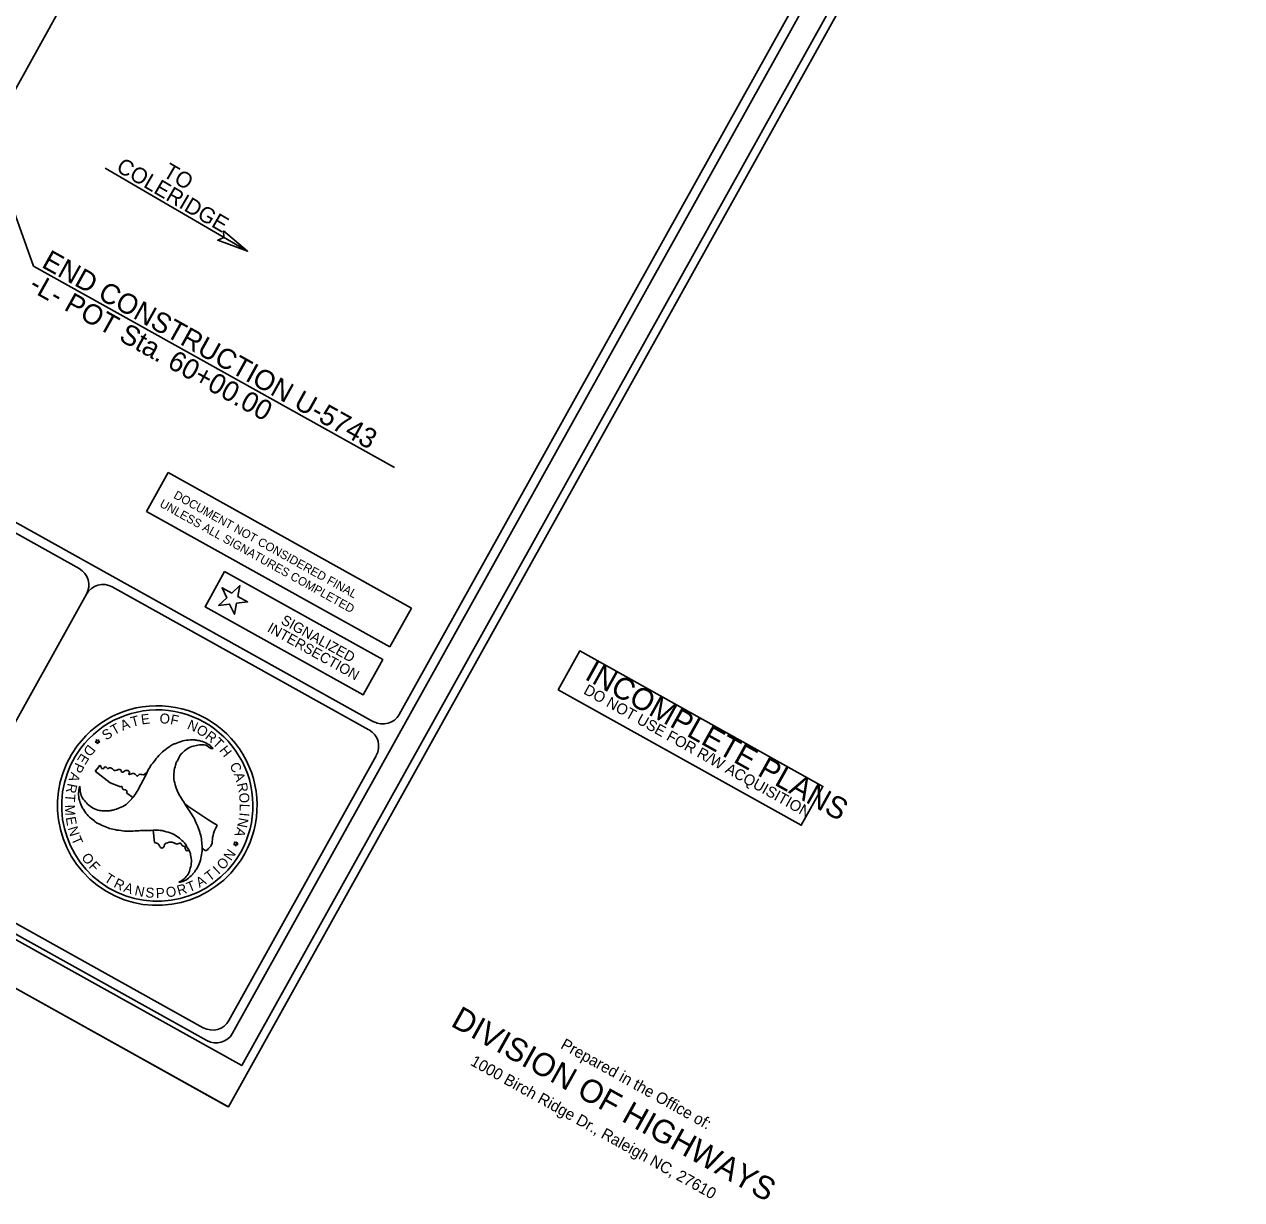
# Model space of a CAD drawing. Extents: x 1754939 to 1770240, y 706534 to 717510.
# Drawn here: x 1766382 to 1770240, y 706534 to 710258 of the extents above; entities that cross this region are included whole.
import ezdxf

# ---------------------------------------------------------------- set-up
doc = ezdxf.new("R2010")
doc.units = 0
for name, color, linetype in [('Culvert Barrel', 7, 'Continuous'), ('Culvert Wing', 7, 'Continuous'), ('ENG SEALS CELL', 7, 'Continuous'), ('Prop Conc 4in Sidewalk', 7, 'Continuous'), ('Prop Conc Drive Radius Type', 7, 'Continuous'), ('Prop EOT Dash', 7, 'Continuous'), ('Prop Guardrail Anchor Unit CELL', 7, 'Continuous'), ('Prop Lane Arrow CELL', 7, 'Continuous'), ('Prop SS Cut Line', 7, 'Continuous'), ('Prop Structure Anchor Unit CELL', 7, 'Continuous'), ('Prop Terminator CELL', 7, 'Continuous'), ('Sheet PE Seal Cell', 7, 'Continuous')]:
    doc.layers.add(name, color=color, linetype=linetype)

msp = doc.modelspace()

# ---------------------------------------------------------------- linework, layer by layer
at = {"layer": 'Culvert Barrel'}
for p, q in [((1758201.2, 711744), (1767028.7, 706828.1)), ((1767026.1, 706829.6), (1758201.2, 711744))]:
    msp.add_line(p, q, dxfattribs=at)
at = {"layer": 'Culvert Wing'}
msp.add_lwpolyline([(1770239.7, 712594.3), (1761412.2, 717510.1), (1758201.2, 711744), (1767028.7, 706828.1)], close=True, dxfattribs=at)
at = {"layer": 'ENG SEALS CELL'}
msp.add_lwpolyline([(1764850.1, 710295.2), (1764850.1, 710295.2), (1765360.9, 711212.6), (1765360.9, 711212.6), (1766611.7, 710516), (1766483.1, 710285.1), (1766100.9, 709598.7)], close=True, dxfattribs=at)
at = {"layer": 'Prop Conc 4in Sidewalk'}
for p, q in [((1766769.2, 708714.5), (1766837.8, 708837.7)), ((1766837.8, 708837.7), (1767608.4, 708408.6)), ((1767539.8, 708285.4), (1766769.2, 708714.5)), ((1767608.3, 708408.5), (1767539.7, 708285.3))]:
    msp.add_line(p, q, dxfattribs=at)
at = {"layer": 'Prop Conc Drive Radius Type'}
for p, q in [((1760044.9, 712193.8), (1767488.6, 708048.6)), ((1765508.2, 709117), (1766555.4, 708533.9)), ((1766660.3, 708475.5), (1767474, 708022.3)), ((1766111.6, 707613.5), (1766578.6, 708452.3)), ((1766606.6, 707983.2), (1766611, 707986.5)), ((1766611.9, 707983.3), (1766606.6, 707983.2)), ((1766611, 707986.5), (1766609.4, 707991.7)), ((1766609.4, 707991.7), (1766613.9, 707988.4)), ((1766613.6, 707978), (1766611.9, 707983.3)), ((1766615.4, 707983.2), (1766613.6, 707978)), ((1766613.9, 707988.4), (1766618.1, 707991.6)), ((1766620.9, 707983.2), (1766615.4, 707983.2)), ((1766618.1, 707991.6), (1766616.6, 707986.4)), ((1766616.6, 707986.4), (1766620.9, 707983.2)), ((1766979.7, 707963.8), (1766978.9, 707963.6)), ((1766979.7, 707963.8), (1766978.9, 707963.6)), ((1766606.6, 707892.2), (1766618.5, 707907.1)), ((1766653.4, 707854.6), (1766606.6, 707892.2)), ((1766687, 707842.1), (1766653.4, 707854.6)), ((1766725.8, 707808), (1766705.9, 707823.2)), ((1766890.8, 707787.8), (1766890.8, 707787.8)), ((1766794.1, 707665.6), (1766790, 707704.5)), ((1766790, 707704.5), (1766790, 707704.5)), ((1767049.2, 707662.3), (1767044.8, 707659)), ((1767051.8, 707664.3), (1767047.5, 707667.5)), ((1767047.5, 707667.5), (1767049.2, 707662.3)), ((1767056.2, 707667.3), (1767051.8, 707664.3)), ((1767054.7, 707662.2), (1767056.2, 707667.3)), ((1767059.1, 707659.1), (1767054.7, 707662.2)), ((1767044.8, 707659), (1767050.1, 707659.1)), ((1767050.1, 707659.1), (1767051.7, 707653.9)), ((1767051.7, 707653.9), (1767053.5, 707659)), ((1767053.5, 707659), (1767059.1, 707659.1)), ((1767056.7, 707594), (1767056.7, 707594))]:
    msp.add_line(p, q, dxfattribs=at)
for points in [[(1767041.7, 707061.2), (1770048.4, 712460.4)], [(1767570.1, 708071.7), (1770007.7, 712448.9)], [(1759201.9, 711358.3), (1766960.1, 707037.9)], [(1767030.1, 707102), (1767497.2, 707940.7)], [(1766134.8, 707531.9), (1766948.5, 707078.8)]]:
    msp.add_lwpolyline(points, dxfattribs=at)
for centre, radius, start, end in [((1766526.2, 708481.5), 60, 330.8875, 60.8875), ((1766631.1, 708423.1), 60, 60.8875, 150.8875), ((1766803.1, 707782.9), 316.3, 323.3087, 143.3087), ((1766803.1, 707782.9), 303.1, 323.3087, 143.3087), ((1767517.9, 708101.2), 60, 240.8875, 330.8875), ((1767444.9, 707970.2), 60, 330.8875, 60.8875), ((1766803.1, 707782.9), 316.3, 143.3087, 323.3087), ((1766803.1, 707782.9), 303.1, 143.3087, 323.3087), ((1767860.9, 709144.3), 1667.7, 228.9872, 229.0868), ((1767860.9, 709144.3), 1667.7, 234.4262, 238.6322), ((1766977.9, 707131.4), 60, 240.8875, 330.8875), ((1766989.5, 707090.6), 60, 240.8875, 330.8875)]:
    msp.add_arc(centre, radius, start, end, dxfattribs=at)
for points in [[(1766978.9, 707963.6), (1766974.3, 707969.4), (1766956.9, 707981.2), (1766935.7, 707988.5), (1766933.6, 707988.8), (1766921.6, 707990.7), (1766907.5, 707990.7), (1766884.1, 707988), (1766861.6, 707979.8), (1766852.3, 707976.1), (1766842.9, 707970), (1766824, 707956.3), (1766808.1, 707941.2), (1766792, 707921.8), (1766779, 707903.8), (1766768.5, 707883.5), (1766758, 707862.9), (1766747.4, 707843.2), (1766736.3, 707823.1), (1766722.9, 707804.9), (1766721.6, 707803.4), (1766704, 707786.5), (1766683.6, 707775.4), (1766662.9, 707768.7), (1766652.1, 707766.6), (1766638.7, 707766.3), (1766631, 707766), (1766615.1, 707768.7), (1766594.7, 707777.6), (1766578.5, 707791.2), (1766566.3, 707806.3), (1766559.4, 707824.6), (1766558, 707844.6)], [(1766871.7, 707539.6), (1766878.7, 707540.8), (1766897.8, 707549.8), (1766914.7, 707564.5), (1766916.2, 707566.1), (1766923.6, 707575.7), (1766930.8, 707588), (1766940.3, 707609.5), (1766944.2, 707633.1), (1766945.8, 707643), (1766945.2, 707654.3), (1766942.8, 707677.5), (1766937.7, 707698.7), (1766928.9, 707722.4), (1766919.6, 707742.5), (1766907.5, 707762), (1766894.9, 707781.2), (1766883.2, 707800.1), (1766871.1, 707820.1), (1766862.2, 707840.7), (1766861.7, 707842.6), (1766855.6, 707866.5), (1766856.3, 707889.7), (1766860.7, 707910.9), (1766864.5, 707921), (1766871, 707932.9), (1766874.5, 707939.9), (1766884.9, 707952), (1766902.8, 707965.4), (1766922.5, 707972.6), (1766941.7, 707975.5), (1766961.1, 707972.3), (1766978.9, 707963.6), (1766979.7, 707963.8)], [(1766618.5, 707907.1), (1766619, 707908.9), (1766622.8, 707908.7), (1766627.8, 707900.4), (1766633.7, 707900.8), (1766635.8, 707904), (1766641, 707905), (1766645.1, 707900.3), (1766653.8, 707902.7), (1766658.6, 707900.6), (1766667.1, 707894.2), (1766684.9, 707896.9), (1766689.6, 707894.3), (1766688.7, 707890.8), (1766690.9, 707888.3), (1766701.6, 707893.5), (1766703.6, 707893.9), (1766713.9, 707891.1), (1766714.9, 707888), (1766712.7, 707883.8), (1766713.2, 707882.2), (1766717.3, 707882.1), (1766724.2, 707884), (1766733.2, 707882.5), (1766740, 707876.1), (1766745.8, 707881.2), (1766758.9, 707880.6), (1766763.3, 707882.8), (1766766.5, 707886)], [(1766768.7, 707884), (1766768.5, 707883.5), (1766758, 707862.9), (1766747.4, 707843.2), (1766736.3, 707823.1), (1766725.7, 707808.1)], [(1766558, 707844.6), (1766555.6, 707837.5), (1766553.9, 707816.6), (1766558, 707794.6), (1766558.9, 707792.7), (1766563.3, 707781.2), (1766570.4, 707769.1), (1766584.4, 707750), (1766602.7, 707735), (1766610.5, 707728.6), (1766620.9, 707723.4), (1766641.9, 707714.1), (1766662.7, 707707.8), (1766687.8, 707703.5), (1766709.6, 707701.4), (1766732.7, 707702.3), (1766755.7, 707703.7), (1766778.1, 707704.2), (1766801.1, 707704.5), (1766823.6, 707702.2), (1766825.8, 707701.5), (1766849.3, 707694.8), (1766868.9, 707682.8), (1766884.9, 707668.5), (1766892.4, 707660), (1766898.9, 707648.5), (1766903.5, 707641.9), (1766908.8, 707626.8), (1766911.2, 707604.8), (1766907.7, 707584.1), (1766900.6, 707565.8), (1766888.2, 707550.7), (1766871.7, 707539.6)], [(1766705.9, 707823.2), (1766706.6, 707828.3), (1766703.6, 707832.4), (1766696.2, 707833.5), (1766692.4, 707836.7), (1766690.4, 707843.1), (1766687, 707842.1)], [(1766946, 707647.1), (1766945.2, 707654.3), (1766942.8, 707677.5), (1766937.7, 707698.7), (1766928.9, 707722.4), (1766919.6, 707742.5), (1766907.5, 707762), (1766894.9, 707781.2), (1766890.8, 707787.8)], [(1766790, 707704.5), (1766801.1, 707704.5), (1766823.6, 707702.2), (1766825.8, 707701.5), (1766849.3, 707694.8), (1766868.9, 707682.8), (1766884.9, 707668.5), (1766892.4, 707660), (1766898.9, 707648.5), (1766903.1, 707642.3)], [(1766992.8, 707720.3), (1766983.8, 707700.7), (1766977.8, 707674.2), (1766975.4, 707659), (1766968.3, 707649.7), (1766957.8, 707640.2), (1766946.1, 707647.1)], [(1766903, 707642.3), (1766897.3, 707639.6), (1766893.3, 707642.1), (1766890.6, 707652.5), (1766881.1, 707656.9), (1766879, 707661.9), (1766876.6, 707663.8), (1766865.1, 707660.8), (1766855.6, 707665), (1766835.3, 707665.1), (1766828.3, 707661.5), (1766820.3, 707648.6), (1766815.2, 707648.6), (1766811.8, 707652.1), (1766806, 707661.3), (1766794.1, 707665.6)]]:
    msp.add_spline(points, degree=3, dxfattribs=at)
at = {"layer": 'Prop EOT Dash'}
msp.add_lwpolyline([(1767016.6, 708524.5), (1767517.9, 708245.4), (1767455.7, 708133.7), (1766954.4, 708412.8)], close=True, dxfattribs=at)
at = {"layer": 'Prop Guardrail Anchor Unit CELL'}
msp.add_lwpolyline([(1767012.5, 709603.5), (1767089.2, 709539.1), (1766994.7, 709573.9), (1767014.4, 709582.7)], close=True, dxfattribs=at)
at = {"layer": 'Prop Lane Arrow CELL'}
msp.add_lwpolyline([(1758334.8, 711823.6), (1767070.6, 706958.9), (1770150.6, 712489.7), (1761414.8, 717354.5), (1758334.8, 711823.6)], dxfattribs=at)
at = {"layer": 'Prop SS Cut Line'}
for p, q in [((1766208.9, 710057.9), (1766410.5, 709491.6)), ((1766410.5, 709491.6), (1767554.9, 708854.4))]:
    msp.add_line(p, q, dxfattribs=at)
at = {"layer": 'Prop Structure Anchor Unit CELL'}
msp.add_lwpolyline([(1767039.3, 708456), (1767008.4, 708473.2), (1767023.2, 708441.1), (1766997.3, 708417), (1767032.5, 708421.2), (1767047.4, 708389.1), (1767054.2, 708423.9), (1767089.3, 708428.1), (1767058.4, 708445.3), (1767065.2, 708480.1), (1767039.3, 708456)], dxfattribs=at)
at = {"layer": 'Prop Terminator CELL'}
msp.add_lwpolyline([(1768073.5, 708149.6), (1768142.1, 708272.8), (1768912.6, 707843.6), (1768844, 707720.5)], close=True, dxfattribs=at)
at = {"layer": 'Sheet PE Seal Cell'}
msp.add_line((1766637.9, 709802.4), (1767089.2, 709539.1), dxfattribs=at)

# ---------------------------------------------------------------- texts
at = {"layer": 'Prop Conc 4in Sidewalk'}
for s, p in [('DOCUMENT NOT CONSIDERED FINAL', (1766852.4, 708758.5)), ('UNLESS ALL SIGNATURES COMPLETED', (1766808.3, 708731.3))]:
    msp.add_text(s, height=27, rotation=330.8875, dxfattribs=at).set_placement(p)
at = {"layer": 'Prop Conc Drive Radius Type'}
for s, height, rotation, p in [('T', 31.6, 28.6888, (1766666, 708005.4)), ('A', 31.6, 21.6365, (1766693.3, 708019.9)), ('T', 31.5, 14.5812, (1766723.6, 708031.9)), ('E', 31.4, 7.4656, (1766753.5, 708039.5)), ('O', 31.6, 355.5262, (1766809.3, 708044)), ('F', 31.6, 348.3794, (1766842.5, 708041.2)), ('N', 31.5, 336.2925, (1766895.6, 708027.3)), ('S', 31.5, 35.0649, (1766641.4, 707988.2)), ('O', 31.6, 328.7943, (1766923.8, 708014.7)), ('R', 31.5, 322.1844, (1766952.3, 707997.4)), ('D', 31.5, 231.1617, (1766585.2, 707978.7)), ('T', 31.6, 315.5348, (1766976.1, 707979)), ('H', 31.5, 308.4501, (1766998, 707957.2)), ('E', 31.4, 237.4496, (1766562.8, 707950.3)), ('P', 31.5, 244.982, (1766544.8, 707921.1)), ('C', 31.4, 296.1077, (1767031.2, 707910.7)), ('A', 31.5, 251.5745, (1766530.6, 707890.5)), ('A', 31.5, 288.6107, (1767044.9, 707882.3)), ('R', 31.5, 282.2467, (1767055.3, 707851.7)), ('T', 31.5, 265.2937, (1766512.7, 707820.8)), ('R', 31.5, 258.6432, (1766519.2, 707854.9)), ('O', 31.6, 275.1271, (1767061.6, 707822.2)), ('M', 31.5, 272.5287, (1766510.2, 707785)), ('L', 31.5, 268.8935, (1767064.6, 707788.8)), ('E', 31.5, 279.9955, (1766512.7, 707745)), ('N', 31.5, 259.204, (1767061.9, 707746.2)), ('I', 31.6, 264.9041, (1767063.5, 707761.5)), ('N', 31.6, 286.9671, (1766519, 707711.5)), ('A', 31.5, 251.772, (1767055.9, 707715.9)), ('T', 31.5, 293.8091, (1766529.7, 707677.6)), ('O', 31.5, 307.1127, (1766560.9, 707618)), ('N', 31.5, 55.5168, (1767036.8, 707605.6)), ('F', 31.5, 314.278, (1766584.3, 707587.9)), ('I', 31.6, 43.1332, (1766997, 707563)), ('O', 31.4, 48.2688, (1767011.7, 707577)), ('T', 31.4, 327.1872, (1766632.2, 707544.7)), ('R', 31.6, 334.1438, (1766662.5, 707525.7)), ('T', 31.4, 22.3118, (1766904, 707507.8)), ('A', 31.6, 30.3988, (1766936.8, 707521.9)), ('T', 31.5, 37.4833, (1766968.9, 707541.2)), ('A', 31.4, 340.897, (1766694, 707510.9)), ('N', 31.4, 347.9286, (1766729.4, 707499.3)), ('S', 31.4, 355.1391, (1766764.5, 707492.5)), ('P', 31.5, 2.3309, (1766799.2, 707489.7)), ('O', 31.6, 9.0229, (1766833, 707491.4)), ('R', 31.6, 16.212, (1766870.6, 707497.6)), ('DIVISION OF HIGHWAYS', 73.123, 330.8875, (1767729.9, 707086.1)), ('Prepared in the Office of:', 35.996, 330.8875, (1768078.7, 707015.4)), ('1000 Birch Ridge Dr., Raleigh NC, 27610', 36, 330.8875, (1767792.6, 706962.3))]:
    msp.add_text(s, height=height, rotation=rotation, dxfattribs=at).set_placement(p)
at = {"layer": 'Prop SS Cut Line'}
for s, p in [('END CONSTRUCTION U-5743', (1766433.2, 709490.4)), ('-L- POT Sta. 60+00.00', (1766392.6, 709417.4))]:
    msp.add_text(s, height=63.75, rotation=330.8875, dxfattribs=at).set_placement(p)
at = {"layer": 'Prop Terminator CELL'}
for s, height, p in [('INCOMPLETE PLANS', 69.12, (1768154.5, 708184.8)), ('DO NOT USE FOR R/W ACQUISITION', 34.56, (1768151.3, 708138.9))]:
    msp.add_text(s, height=height, rotation=330.8875, dxfattribs=at).set_placement(p)
at = {"layer": 'Sheet PE Seal Cell'}
for s, height, rotation, p in [('COLERIDGE', 50, 329.7417, (1766669.6, 709795.1)), ('TO ', 50, 329.7417, (1766817.5, 709778.3)), ('INTERSECTION', 32.5, 330.8875, (1767149.1, 708335.9)), ('SIGNALIZED', 32.5, 330.8875, (1767192.4, 708360.5))]:
    msp.add_text(s, height=height, rotation=rotation, dxfattribs=at).set_placement(p)

doc.saveas('drawing.dxf')
